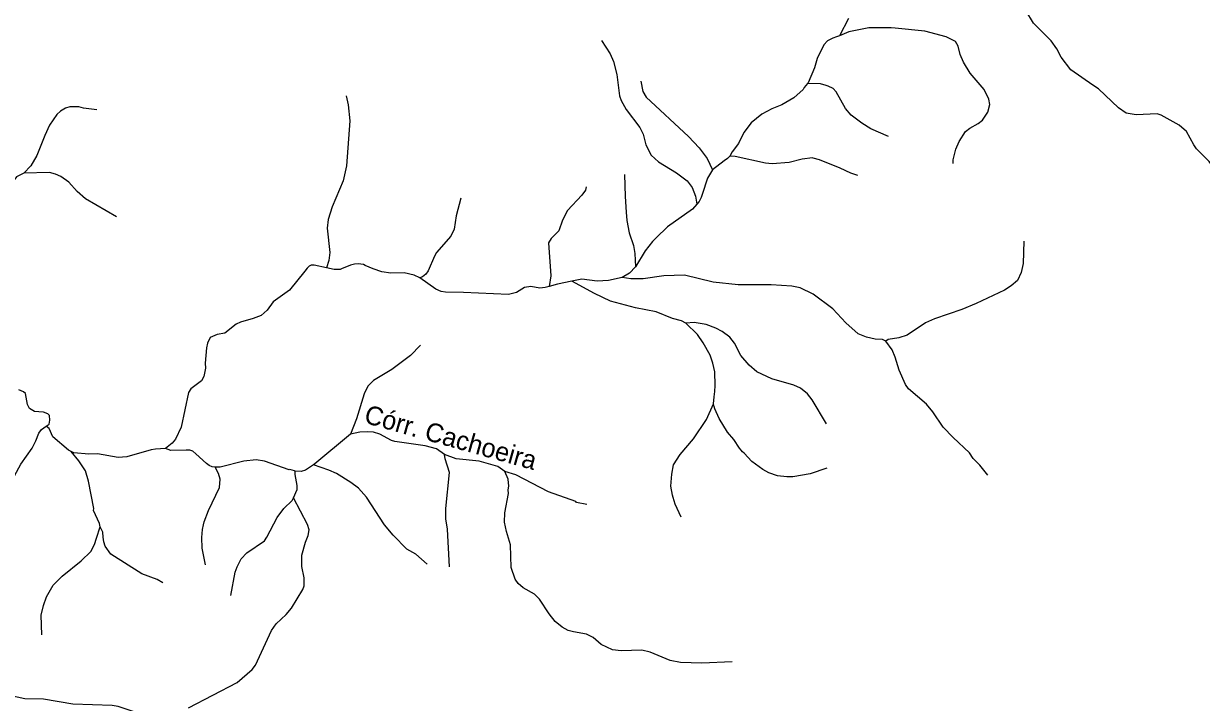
# Model space of a CAD drawing. Extents: x 280.4 to 335.6, y 8893.9 to 8949.5.
# Drawn here: x 314.12 to 324.16, y 8932.34 to 8938.13 of the extents above; entities that cross this region are included whole.
import ezdxf
from ezdxf.enums import TextEntityAlignment as Align

# ---------------------------------------------------------------- set-up
doc = ezdxf.new("R2010")
doc.units = 0
doc.header["$LTSCALE"] = 0.064
doc.layers.add('61', color=7, linetype='Continuous')
doc.layers.add('7', color=7, linetype='Continuous', lineweight=25)

msp = doc.modelspace()

# ---------------------------------------------------------------- linework, layer by layer
at = {"layer": '7'}
msp.add_line((321.1556, 8938.1677), (321.0782, 8938.0222), dxfattribs=at)
for points in [[(324.3247, 8936.7933), (324.2839, 8936.8741), (324.2316, 8936.9501), (324.123, 8937.0588), (324.0994, 8937.0913), (324.0374, 8937.2065), (323.9741, 8937.2603), (323.8223, 8937.3458), (323.7861, 8937.3561), (323.6088, 8937.3468), (323.5223, 8937.3626), (323.4581, 8937.4067), (323.2859, 8937.5679), (323.238, 8937.6015), (323.0515, 8937.7322), (322.9671, 8937.8387), (322.9325, 8937.9103), (322.8823, 8937.9794), (322.7308, 8938.1293), (322.6665, 8938.2375), (322.6008, 8938.3979)], [(322.0464, 8936.9319), (322.0466, 8936.9654), (322.0706, 8937.0542), (322.0976, 8937.1214), (322.1519, 8937.2067), (322.19, 8937.235), (322.2609, 8937.2728), (322.2962, 8937.3018), (322.3428, 8937.3692), (322.3588, 8937.4356), (322.352, 8937.4824), (322.3128, 8937.5634), (322.1915, 8937.7028), (322.1351, 8937.7978), (322.1077, 8937.8624), (322.0886, 8937.932), (322.0665, 8937.9714), (321.9863, 8938.0136), (321.8062, 8938.0598), (321.5513, 8938.0853), (321.5177, 8938.0887), (321.3275, 8938.0885), (321.1578, 8938.0556), (321.0782, 8938.0222)], [(319.0472, 8937.9824), (319.1204, 8937.8681), (319.1491, 8937.801), (319.1777, 8937.6904), (319.2003, 8937.5105), (319.2154, 8937.4689), (319.2576, 8937.393), (319.3757, 8937.2407), (319.4033, 8937.1818), (319.4272, 8937.0915), (319.4727, 8937.0031), (319.5345, 8936.9461), (319.6866, 8936.8519), (319.7773, 8936.7857), (319.8216, 8936.7277), (319.8481, 8936.6548), (319.8559, 8936.6202), (319.8599, 8936.5869)], [(321.0782, 8938.0222), (321.051, 8938.0121), (321.0213, 8938.0004), (320.9759, 8937.9785), (320.943, 8937.9434), (320.8881, 8937.827), (320.865, 8937.749), (320.809, 8937.6198), (320.8047, 8937.6149)], [(319.3834, 8937.6344), (319.4004, 8937.5459), (319.4291, 8937.4982), (319.79, 8937.1633), (319.8811, 8937.0658), (319.9503, 8936.9741), (319.9934, 8936.88)], [(320.8047, 8937.6149), (320.7753, 8937.5812), (320.7685, 8937.5623), (320.6887, 8937.4914), (320.5868, 8937.4338), (320.5006, 8937.3979), (320.4152, 8937.3527), (320.3231, 8937.2795), (320.2617, 8937.1978), (320.2162, 8937.1043), (320.1635, 8937.0321), (320.1412, 8936.9959)], [(321.4949, 8937.1643), (321.3458, 8937.2285), (321.2688, 8937.276), (321.1776, 8937.3447), (321.1276, 8937.4012), (321.0496, 8937.5438), (321.0247, 8937.572), (320.9813, 8937.5913), (320.9641, 8937.5989), (320.9164, 8937.6106), (320.8047, 8937.6149)], [(316.8699, 8937.5106), (316.8862, 8937.4325), (316.9007, 8937.2973), (316.8716, 8936.9133), (316.8437, 8936.7842), (316.7517, 8936.5624), (316.7164, 8936.4558), (316.7073, 8936.3822), (316.7294, 8936.1753), (316.7213, 8936.105), (316.702, 8936.0443)], [(314.7435, 8937.3913), (314.6307, 8937.4043), (314.589, 8937.4155), (314.5136, 8937.4156), (314.4767, 8937.4044), (314.4322, 8937.3777), (314.4018, 8937.3507), (314.3409, 8937.2585), (314.2989, 8937.1715), (314.2305, 8936.9996), (314.1797, 8936.9127), (314.1208, 8936.8518)], [(320.1412, 8936.9959), (320.1211, 8936.9744), (320.0936, 8936.9562), (319.9934, 8936.88)], [(321.2353, 8936.8305), (321.1746, 8936.8503), (321.0846, 8936.8931), (320.9066, 8936.9633), (320.8533, 8936.9784), (320.8459, 8936.9805), (320.7603, 8936.971), (320.6493, 8936.9424), (320.5031, 8936.931), (320.4455, 8936.9359), (320.1887, 8936.993), (320.1412, 8936.9959)], [(319.9934, 8936.88), (319.9518, 8936.8086), (319.907, 8936.6682), (319.8989, 8936.6417), (319.8793, 8936.6101), (319.8599, 8936.5869)], [(314.1208, 8936.8518), (314.0579, 8936.8183), (314.0433, 8936.8004), (313.9013, 8936.734), (313.6711, 8936.6538), (313.6327, 8936.6313), (313.5044, 8936.5109), (313.286, 8936.2378)], [(314.9105, 8936.4782), (314.6474, 8936.6304), (314.5758, 8936.6953), (314.5049, 8936.7726), (314.4364, 8936.8227), (314.3921, 8936.8426), (314.3387, 8936.8558), (314.1208, 8936.8518)], [(319.2451, 8936.838), (319.2485, 8936.6513), (319.2578, 8936.5183), (319.2628, 8936.4479), (319.2834, 8936.3432), (319.3193, 8936.2338), (319.3316, 8936.1657), (319.3382, 8936.0531)], [(318.9161, 8936.7331), (318.9111, 8936.7067), (318.8795, 8936.6643), (318.7579, 8936.5316), (318.7165, 8936.4509), (318.685, 8936.3595), (318.6195, 8936.294), (318.5947, 8936.2576), (318.6149, 8935.976), (318.6002, 8935.8839)], [(317.848, 8936.6379), (317.8092, 8936.4868), (317.7899, 8936.3719), (317.7641, 8936.3122), (317.6408, 8936.1754), (317.622, 8936.1441), (317.5694, 8936.0168), (317.549, 8935.9887), (317.5224, 8935.9674), (317.4976, 8935.9592)], [(319.8599, 8936.5869), (319.8243, 8936.5444), (319.6095, 8936.3929), (319.5152, 8936.3001), (319.4838, 8936.2692), (319.4211, 8936.1888), (319.3382, 8936.0531)], [(322.6501, 8936.2699), (322.6452, 8936.0801), (322.628, 8936.0048), (322.5963, 8935.9371), (322.5407, 8935.8894), (322.4853, 8935.8538), (322.2444, 8935.7397), (322.1198, 8935.6898), (321.888, 8935.6093), (321.8117, 8935.5738), (321.6558, 8935.4697), (321.5834, 8935.4481), (321.4929, 8935.434), (321.4737, 8935.419)], [(316.702, 8936.0443), (316.5973, 8936.0664), (316.5729, 8936.0655), (316.5537, 8936.0576)], [(317.4976, 8935.9592), (317.4502, 8935.9813), (317.366, 8936), (317.2509, 8935.9986), (317.1742, 8936.0098), (317.099, 8936.0347), (317.0327, 8936.0645), (317.0189, 8936.0707), (316.9736, 8936.0769), (316.9407, 8936.0747), (316.9063, 8936.0674), (316.8295, 8936.0341), (316.8177, 8936.0307), (316.7943, 8936.0291), (316.768, 8936.0298), (316.702, 8936.0443)], [(316.5537, 8936.0576), (316.5372, 8936.042), (316.518, 8936.0163), (316.3878, 8935.852), (316.2488, 8935.7543), (316.1953, 8935.682), (316.146, 8935.6369), (316.0768, 8935.6108), (315.9676, 8935.5808), (315.9325, 8935.5646), (315.8352, 8935.4871), (315.7692, 8935.4753), (315.7103, 8935.4488), (315.6876, 8935.4005), (315.6789, 8935.3628), (315.6679, 8935.2306), (315.6707, 8935.1877), (315.655, 8935.1181), (315.6348, 8935.0813), (315.5451, 8935.0139), (315.5242, 8934.9804), (315.4623, 8934.6871), (315.4133, 8934.5833), (315.3871, 8934.5491), (315.3287, 8934.5041)], [(319.3382, 8936.0531), (319.2872, 8935.9991), (319.225, 8935.9604)], [(321.4737, 8935.419), (321.4448, 8935.4336), (321.3822, 8935.4371), (321.3074, 8935.4515), (321.2372, 8935.481), (321.1313, 8935.5742), (321.0203, 8935.6931), (320.8524, 8935.8194), (320.7412, 8935.8719), (320.6709, 8935.8865), (320.4942, 8935.8994), (320.212, 8935.8995), (320.0009, 8935.9221), (319.7546, 8935.9825), (319.5787, 8935.9761), (319.4035, 8935.9506), (319.2979, 8935.9506), (319.225, 8935.9604)], [(318.6002, 8935.8839), (318.5672, 8935.8748), (318.5208, 8935.8708), (318.4447, 8935.8849), (318.3906, 8935.8765), (318.3237, 8935.8321), (318.2551, 8935.8151), (317.87, 8935.8338), (317.7178, 8935.8353), (317.6815, 8935.8423), (317.6352, 8935.8611), (317.4976, 8935.9592)], [(318.7935, 8935.9289), (318.6711, 8935.9034), (318.6002, 8935.8839)], [(319.225, 8935.9604), (319.2242, 8935.9599), (319.1076, 8935.9348), (319.0108, 8935.9298), (318.8798, 8935.9469), (318.7935, 8935.9289)], [(319.766, 8935.5729), (319.7287, 8935.592), (319.6545, 8935.6106), (319.5129, 8935.6688), (319.3371, 8935.7042), (319.1252, 8935.7603), (318.9866, 8935.8247), (318.7935, 8935.9289)], [(320.9667, 8934.7141), (320.8437, 8934.9177), (320.8044, 8934.9686), (320.745, 8935.0172), (320.6868, 8935.0451), (320.5, 8935.0968), (320.3714, 8935.1568), (320.3068, 8935.2137), (320.2356, 8935.2959), (320.181, 8935.4013), (320.1412, 8935.4526), (320.0779, 8935.5017), (320.0234, 8935.5302), (319.9408, 8935.5603), (319.8378, 8935.5764), (319.766, 8935.5729)], [(320.0027, 8934.8851), (320.01, 8934.9448), (320.0132, 8934.9887), (320.0177, 8935.0422), (320.0129, 8935.1572), (319.998, 8935.231), (319.9757, 8935.3003), (319.9156, 8935.4046), (319.8656, 8935.4756), (319.766, 8935.5729)], [(317.5053, 8935.3854), (317.4182, 8935.2964), (317.2606, 8935.1772), (317.104, 8935.0828), (317.0545, 8935.0342), (317.0236, 8934.9712), (316.9582, 8934.756), (316.907, 8934.6251)], [(322.3436, 8934.2766), (322.275, 8934.3619), (322.2446, 8934.3931), (322.2183, 8934.4201), (322.187, 8934.467), (322.046, 8934.5971), (321.9613, 8934.6866), (321.8741, 8934.8159), (321.8204, 8934.8817), (321.6649, 8935.0135), (321.6416, 8935.0486), (321.5855, 8935.1702), (321.5528, 8935.2825), (321.5256, 8935.3444), (321.4737, 8935.419)], [(314.31, 8934.6935), (314.3362, 8934.7121), (314.3424, 8934.7444), (314.3398, 8934.7858), (314.3265, 8934.8008), (314.2883, 8934.8136), (314.2494, 8934.8163), (314.2119, 8934.8189), (314.1686, 8934.8448), (314.1516, 8934.8782), (314.1353, 8934.9717), (314.1186, 8934.9867), (314.0779, 8935.0037)], [(319.7277, 8933.9187), (319.6754, 8934.0299), (319.6585, 8934.0874), (319.6531, 8934.1059), (319.6402, 8934.1834), (319.6463, 8934.2842), (319.6618, 8934.3638), (319.7186, 8934.4515), (319.8317, 8934.5875), (319.9421, 8934.7521), (320.0027, 8934.8851)], [(320.9688, 8934.3359), (320.8273, 8934.2874), (320.6797, 8934.2618), (320.627, 8934.2619), (320.5477, 8934.2723), (320.4757, 8934.2967), (320.4237, 8934.3249), (320.33, 8934.3941), (320.2636, 8934.4644), (320.2508, 8934.4758), (320.2375, 8934.4906), (320.2234, 8934.5064), (320.1759, 8934.58), (320.1216, 8934.644), (320.0513, 8934.7592), (320.0148, 8934.8412), (320.0087, 8934.8607), (320.0027, 8934.8851)], [(313.9145, 8933.7838), (313.9461, 8933.8255), (313.9647, 8933.8611), (313.9884, 8933.9307), (313.9979, 8934.0003), (313.9918, 8934.0714), (313.9983, 8934.1425), (314.0409, 8934.2716), (314.0962, 8934.3707), (314.1908, 8934.5079), (314.2227, 8934.5689), (314.2479, 8934.635), (314.2716, 8934.6662), (314.31, 8934.6935)], [(314.5239, 8934.4787), (314.5026, 8934.4896), (314.3669, 8934.6034), (314.3356, 8934.6738), (314.31, 8934.6935)], [(316.907, 8934.6251), (316.6029, 8934.3742), (316.59, 8934.3654)], [(317.7095, 8934.4531), (317.6394, 8934.5003), (317.5444, 8934.5257), (317.2853, 8934.5627), (317.2555, 8934.5729), (317.1581, 8934.6263), (317.1021, 8934.642), (317.0496, 8934.6468), (316.9854, 8934.6423), (316.907, 8934.6251)], [(315.3287, 8934.5041), (315.2446, 8934.4975), (315.2071, 8934.492), (314.9989, 8934.432), (314.9248, 8934.4266), (314.7504, 8934.4599), (314.6743, 8934.4554), (314.5466, 8934.4671), (314.5239, 8934.4787)], [(314.7717, 8933.8358), (314.7667, 8933.8641), (314.7149, 8933.9743), (314.7173, 8933.9929), (314.6732, 8934.2265), (314.6456, 8934.3145), (314.5886, 8934.4003), (314.5239, 8934.4787)], [(315.7534, 8934.3445), (315.7262, 8934.349), (315.7011, 8934.3599), (315.6782, 8934.3774), (315.5876, 8934.4584), (315.5624, 8934.4801), (315.5375, 8934.4885), (315.5067, 8934.491), (315.3757, 8934.4877), (315.3516, 8934.4943), (315.3287, 8934.5041)], [(316.4351, 8934.312), (316.4282, 8934.3141), (316.3893, 8934.3258), (316.3825, 8934.3217), (316.1737, 8934.3958), (316.1034, 8934.4072), (315.9978, 8934.3947), (315.7952, 8934.3463), (315.7534, 8934.3445)], [(316.59, 8934.3654), (316.5231, 8934.3202), (316.486, 8934.3084), (316.4351, 8934.312)], [(317.5618, 8933.5192), (317.4636, 8933.6027), (317.3872, 8933.6472), (317.2697, 8933.7666), (317.1979, 8933.8534), (317.0448, 8934.0901), (316.9746, 8934.1669), (316.9107, 8934.2149), (316.7877, 8934.2902), (316.7234, 8934.3197), (316.59, 8934.3654)], [(318.2242, 8934.3088), (318.1639, 8934.351), (318.0054, 8934.3972), (317.809, 8934.4157), (317.7095, 8934.4531)], [(317.7503, 8933.4946), (317.7352, 8933.8172), (317.7211, 8933.9051), (317.721, 8933.9939), (317.7514, 8934.2989), (317.7151, 8934.4153), (317.7095, 8934.4531)], [(315.671, 8933.5116), (315.6425, 8933.6549), (315.6388, 8933.7445), (315.6437, 8933.8148), (315.653, 8933.8523), (315.6599, 8933.8802), (315.6964, 8933.9755), (315.7897, 8934.1703), (315.7954, 8934.2434), (315.7804, 8934.2904), (315.7534, 8934.3445)], [(316.4212, 8934.0841), (316.4512, 8934.1554), (316.4509, 8934.1882), (316.4338, 8934.2818), (316.4351, 8934.312)], [(320.1609, 8932.6848), (319.9031, 8932.6738), (319.7219, 8932.6802), (319.6324, 8932.6981), (319.4633, 8932.7678), (319.3914, 8932.7853), (319.2165, 8932.7793), (319.1426, 8932.7886), (319.0459, 8932.8339), (318.977, 8932.8923), (318.9199, 8932.9216), (318.8076, 8932.9403), (318.7648, 8932.9544), (318.7127, 8932.9824), (318.6519, 8933.0288), (318.6007, 8933.0944), (318.5186, 8933.2196), (318.4753, 8933.2626), (318.3794, 8933.317), (318.3367, 8933.3532), (318.3124, 8933.3911), (318.2777, 8933.49), (318.271, 8933.6819), (318.2363, 8933.7969), (318.2201, 8933.8761), (318.2236, 8933.9554), (318.2551, 8934.1194), (318.2522, 8934.1514), (318.2583, 8934.1842), (318.2522, 8934.2426), (318.2242, 8934.3088)], [(318.9216, 8934.027), (318.8356, 8934.0442), (318.8287, 8934.0514), (318.5943, 8934.1355), (318.3177, 8934.2785), (318.2242, 8934.3088)], [(315.5249, 8932.2946), (315.9411, 8932.509), (316.0675, 8932.621), (316.0969, 8932.6589), (316.2328, 8932.9529), (316.2726, 8933.0084), (316.358, 8933.0891), (316.4045, 8933.1439), (316.5018, 8933.3019), (316.512, 8933.3331), (316.512, 8933.4022), (316.4929, 8933.499), (316.4929, 8933.5941), (316.5228, 8933.7054), (316.5469, 8933.7639), (316.5536, 8933.8112), (316.5389, 8933.8577), (316.4212, 8934.0841)], [(315.8868, 8933.2509), (315.9234, 8933.4503), (315.939, 8933.4954), (315.9747, 8933.5644), (316.0237, 8933.6152), (316.1733, 8933.7169), (316.1947, 8933.7472), (316.2801, 8933.9158), (316.3393, 8933.9914), (316.4095, 8934.0605), (316.4212, 8934.0841)], [(314.2756, 8932.9155), (314.27, 8933.0831), (314.2885, 8933.1664), (314.3129, 8933.2391), (314.3723, 8933.3389), (314.4475, 8933.4173), (314.6094, 8933.5458), (314.6916, 8933.6263), (314.7234, 8933.6846), (314.7411, 8933.7399), (314.7717, 8933.8358)], [(315.3066, 8933.3588), (315.2575, 8933.388), (315.1274, 8933.4348), (314.8638, 8933.6025), (314.8141, 8933.6726), (314.8025, 8933.7085), (314.7984, 8933.7485), (314.7942, 8933.7898), (314.7717, 8933.8358)], [(315.182, 8932.2188), (314.9256, 8932.3041), (314.8737, 8932.3151), (314.539, 8932.3247), (314.289, 8932.3666), (314.1286, 8932.3719), (313.9981, 8932.4003), (313.914, 8932.4383), (313.8707, 8932.4512), (313.8327, 8932.4541), (313.7805, 8932.4482), (313.6447, 8932.4144), (313.5328, 8932.4084), (313.4664, 8932.4229), (313.3641, 8932.4699)]]:
    msp.add_lwpolyline(points, dxfattribs=at)

# ---------------------------------------------------------------- texts
at = {"layer": '61'}
msp.add_text('Córr. Cachoeira', height=0.16, rotation=344.392, dxfattribs=at).set_placement((317.7412, 8934.5225), align=Align.CENTER)

doc.saveas('drawing.dxf')
